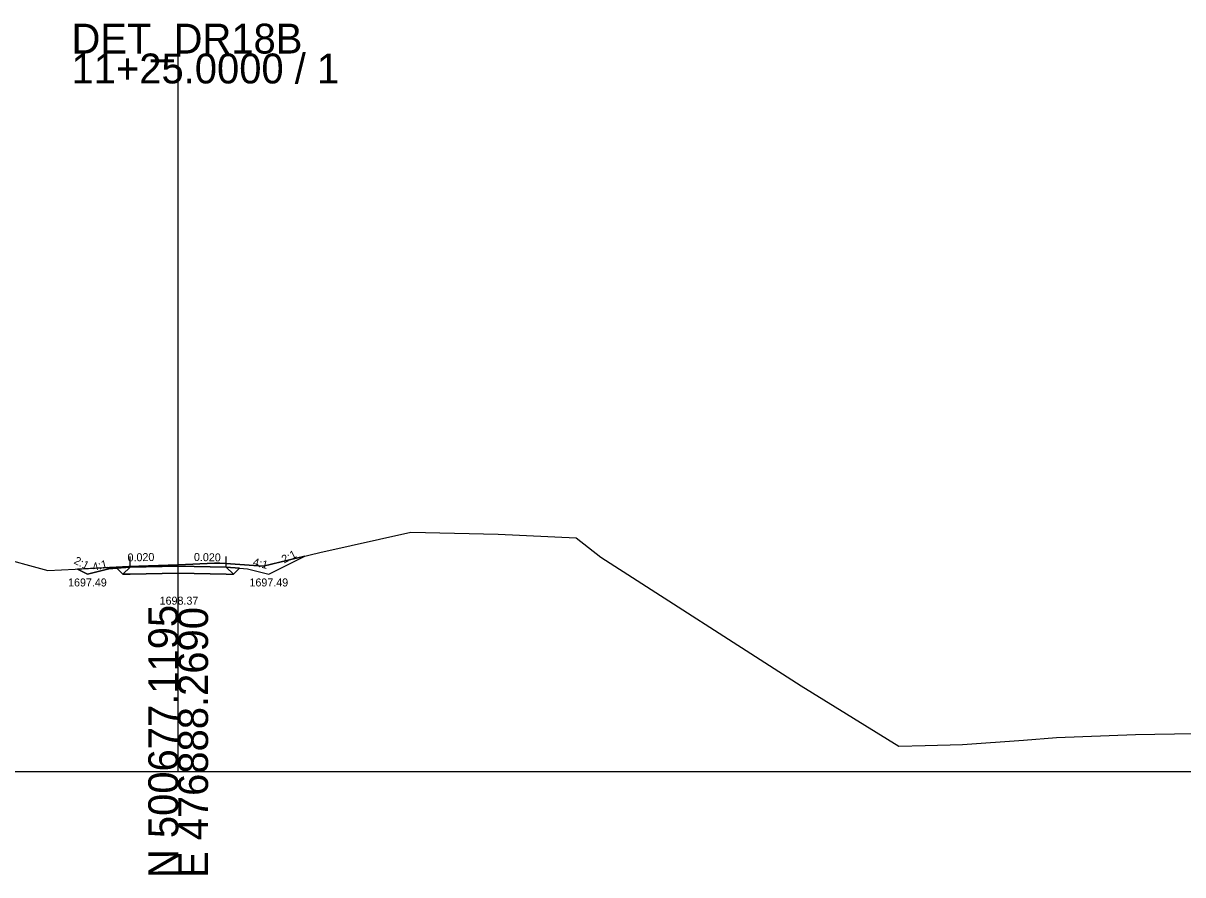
# Model space of a CAD drawing. Extents: x -26 to 403, y -10 to 2570.
# Drawn here: x 185.5 to 294.2, y 2490.3 to 2570.1 of the extents above; entities that cross this region are included whole.
import ezdxf

# ---------------------------------------------------------------- set-up
doc = ezdxf.new("R2010")
doc.units = 0
for name, color, linetype in [('Exist Cross Section Cell', 7, 'Continuous'), ('Exist XS Center Line Elevation Label', 7, 'Continuous'), ('Exist XS Ground Line', 7, 'Continuous'), ('Prop XS Ditch Slope Text', 7, 'Continuous'), ('Prop XS Ditch Standard Text', 7, 'Continuous'), ('Prop XS Dump Level', 7, 'Continuous'), ('Prop XS Earthwork Shape', 7, 'Continuous'), ('Prop XS EOT Tick Mark', 7, 'Continuous'), ('Prop XS Finish Grade', 7, 'Continuous'), ('Prop XS Finish Grade Earthwork', 7, 'Continuous'), ('Prop XS Finish Grade Pavement', 7, 'Continuous'), ('Prop XS Hydro Typical Ditch Data', 7, 'Continuous'), ('Prop XS Pvmt Edge Slope', 7, 'Continuous'), ('Prop XS SE Text', 7, 'Continuous'), ('Prop XS Shoulder Borrow Shape', 7, 'Continuous'), ('Prop XS Side Slope Text', 7, 'Continuous'), ('Prop XS Subgrade Earthwork', 7, 'Continuous')]:
    doc.layers.add(name, color=color, linetype=linetype)

msp = doc.modelspace()

# ---------------------------------------------------------------- linework, layer by layer
at = {"layer": 'Exist Cross Section Cell'}
for p, q in [((200, 2500), (200, 2567.27)), ((0, 2500), (200, 2500)), ((200, 2500), (400, 2500))]:
    msp.add_line(p, q, dxfattribs=at)
at = {"layer": 'Exist XS Ground Line'}
msp.add_lwpolyline([(182.73, 2520.19), (187.78, 2518.81), (190.33, 2518.95), (195.37, 2519.2), (200, 2519.37), (203.4, 2519.5), (203.89, 2519.52), (204.47, 2519.47), (207.97, 2519.23), (213.28, 2520.52), (221.79, 2522.42), (230, 2522.23), (237.29, 2521.89), (239.6, 2520.06), (258.39, 2508.03), (267.55, 2502.36), (270.01, 2502.44), (273.5, 2502.53), (279.24, 2502.94), (282.32, 2503.19), (289.72, 2503.47), (304.32, 2503.72)], dxfattribs=at)
at = {"layer": 'Prop XS Dump Level'}
for p, q in [((200, 2519.24), (195.5, 2519.15)), ((195.5, 2519.15), (200, 2519.24)), ((204.5, 2519.15), (200, 2519.24)), ((200, 2519.24), (204.5, 2519.15))]:
    msp.add_line(p, q, dxfattribs=at)
at = {"layer": 'Prop XS Earthwork Shape'}
msp.add_lwpolyline([(204.5, 2518.48), (205.18, 2518.47), (205.76, 2519.05), (206.5, 2518.99), (208.5, 2518.49), (211.88, 2520.18), (207.97, 2519.23), (204.47, 2519.47), (203.89, 2519.52), (203.4, 2519.5), (200, 2519.37), (195.37, 2519.2), (190.55, 2518.96), (191.5, 2518.49), (193.5, 2518.99), (194.24, 2519.05), (194.82, 2518.47), (195.5, 2518.48), (200, 2518.57)], close=True, dxfattribs=at)
at = {"layer": 'Prop XS EOT Tick Mark'}
for p, q in [((195.5, 2519.15), (195.5, 2520.15)), ((204.5, 2519.15), (204.5, 2520.15))]:
    msp.add_line(p, q, dxfattribs=at)
at = {"layer": 'Prop XS Finish Grade'}
for p, q in [((195.5, 2519.15), (194.24, 2519.05)), ((204.5, 2519.15), (205.76, 2519.05))]:
    msp.add_line(p, q, dxfattribs=at)
at = {"layer": 'Prop XS Finish Grade Earthwork'}
for p, q in [((208.5, 2518.49), (211.88, 2520.18)), ((191.5, 2518.49), (190.55, 2518.96)), ((193.5, 2518.99), (191.5, 2518.49)), ((194.24, 2519.05), (193.5, 2518.99)), ((205.76, 2519.05), (206.5, 2518.99)), ((206.5, 2518.99), (208.5, 2518.49))]:
    msp.add_line(p, q, dxfattribs=at)
at = {"layer": 'Prop XS Finish Grade Pavement'}
for p, q in [((195.5, 2519.15), (200, 2519.24)), ((200, 2519.24), (204.5, 2519.15))]:
    msp.add_line(p, q, dxfattribs=at)
at = {"layer": 'Prop XS Hydro Typical Ditch Data'}
for p, q in [((208.5, 2518.49), (211.88, 2520.18)), ((191.5, 2518.49), (190.55, 2518.96)), ((193.5, 2518.99), (191.5, 2518.49)), ((206.5, 2518.99), (208.5, 2518.49))]:
    msp.add_line(p, q, dxfattribs=at)
at = {"layer": 'Prop XS Pvmt Edge Slope'}
for p, q in [((195.5, 2519.15), (194.82, 2518.47)), ((204.5, 2519.15), (205.18, 2518.47))]:
    msp.add_line(p, q, dxfattribs=at)
at = {"layer": 'Prop XS Shoulder Borrow Shape'}
for points in [[(195.5, 2519.15), (194.82, 2518.47), (194.24, 2519.05)], [(205.18, 2518.47), (205.76, 2519.05), (204.5, 2519.15)]]:
    msp.add_lwpolyline(points, close=True, dxfattribs=at)
at = {"layer": 'Prop XS Subgrade Earthwork'}
for p, q in [((194.82, 2518.47), (194.24, 2519.05)), ((195.5, 2518.48), (194.82, 2518.47)), ((200, 2518.57), (195.5, 2518.48)), ((204.5, 2518.48), (200, 2518.57)), ((204.5, 2518.48), (205.18, 2518.47)), ((205.18, 2518.47), (205.76, 2519.05))]:
    msp.add_line(p, q, dxfattribs=at)

# ---------------------------------------------------------------- texts
at = {"layer": 'Exist Cross Section Cell'}
for s, p in [('DET_DR18B', (190, 2567.27)), ('11+25.0000 / 1', (190, 2564.47))]:
    msp.add_text(s, height=2.8, dxfattribs=at).set_placement(p)
for s, p in [('N 500677.1195', (200, 2490)), ('E 476888.2690', (202.8, 2490))]:
    msp.add_text(s, height=2.8, rotation=90, dxfattribs=at).set_placement(p)
at = {"layer": 'Exist XS Center Line Elevation Label'}
msp.add_text('1698.37', height=0.75, dxfattribs=at).set_placement((198.26, 2515.62))
at = {"layer": 'Prop XS Ditch Slope Text'}
for rotation, p in [(14.0362, (192.06, 2518.77)), (345.9638, (206.95, 2519.3))]:
    msp.add_text('4:1', height=0.75, rotation=rotation, dxfattribs=at).set_placement(p)
at = {"layer": 'Prop XS Ditch Standard Text'}
for p in [(189.68, 2517.33), (206.68, 2517.33)]:
    msp.add_text('1697.49', height=0.75, dxfattribs=at).set_placement(p)
at = {"layer": 'Prop XS Dump Level'}
for p in [(193.5, 2518.95), (206.5, 2518.95)]:
    msp.add_text('Case1', height=0.04, dxfattribs=at).set_placement(p)
at = {"layer": 'Prop XS SE Text'}
for rotation, p in [(1.1458, (195.26, 2519.67)), (358.8542, (201.47, 2519.72))]:
    msp.add_text('0.020', height=0.75, rotation=rotation, dxfattribs=at).set_placement(p)
at = {"layer": 'Prop XS Side Slope Text'}
for rotation, p in [(26.5651, (209.92, 2519.48)), (333.4349, (190.16, 2519.51))]:
    msp.add_text('2:1', height=0.75, rotation=rotation, dxfattribs=at).set_placement(p)

doc.saveas('drawing.dxf')
